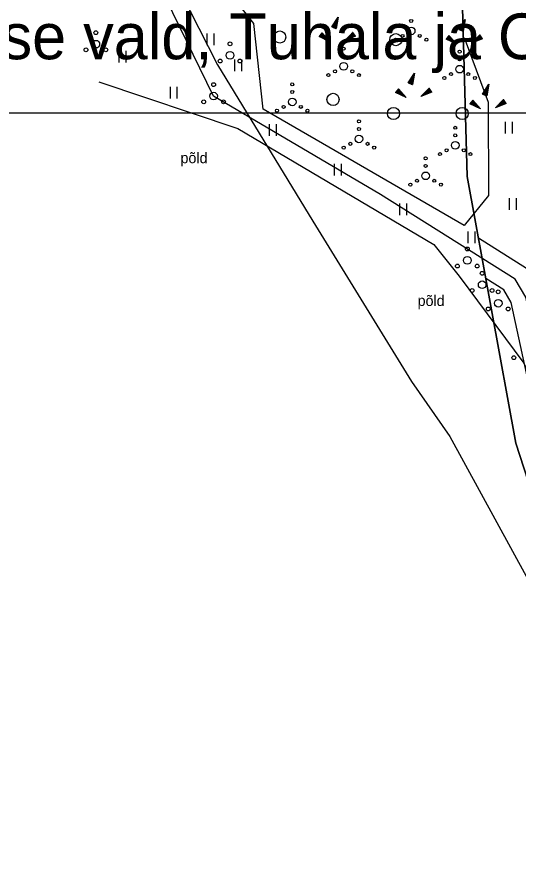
# Model space of a CAD drawing. Extents: x 554947 to 555436, y 6564938 to 6565792.
# Drawn here: x 555027.7 to 555060.6, y 6565555.5 to 6565611.2 of the extents above; entities that cross this region are included whole.
import ezdxf

# ---------------------------------------------------------------- set-up
doc = ezdxf.new("R2010")
doc.units = 0
for name, color, linetype in [('HALJASTUS', 7, 'Continuous'), ('KASUTUSALA', 7, 'Continuous'), ('KPKAABEL', 7, 'Continuous'), ('PIIR', 7, 'Continuous'), ('PR_SIDE', 7, 'Continuous'), ('PUU', 7, 'Continuous'), ('RELJEEF', 7, 'Continuous'), ('VORMISTUS_2', 7, 'Continuous')]:
    doc.layers.add(name, color=color, linetype=linetype)

msp = doc.modelspace()

# ---------------------------------------------------------------- linework, layer by layer
at = {"layer": 'HALJASTUS'}
for p, q in [((555040.145, 6565610.116), (555040.145, 6565609.355)), ((555040.6, 6565610.116), (555040.6, 6565609.355)), ((555034.383, 6565608.969), (555034.383, 6565608.208)), ((555034.838, 6565608.969), (555034.838, 6565608.208)), ((555041.957, 6565608.406), (555041.957, 6565607.645)), ((555042.412, 6565608.406), (555042.412, 6565607.645)), ((555037.737, 6565606.607), (555037.737, 6565605.846)), ((555038.192, 6565606.607), (555038.192, 6565605.846)), ((555044.239, 6565604.173), (555044.239, 6565603.412)), ((555044.694, 6565604.173), (555044.694, 6565603.412)), ((555059.719, 6565604.314), (555059.719, 6565603.553)), ((555060.174, 6565604.314), (555060.174, 6565603.553)), ((555048.509, 6565601.572), (555048.509, 6565600.811)), ((555048.964, 6565601.572), (555048.964, 6565600.811)), ((555059.968, 6565599.32), (555059.968, 6565598.559)), ((555060.423, 6565599.32), (555060.423, 6565598.559)), ((555052.779, 6565598.971), (555052.779, 6565598.209)), ((555053.234, 6565598.971), (555053.234, 6565598.209)), ((555057.264, 6565597.135), (555057.264, 6565596.374)), ((555057.719, 6565597.135), (555057.719, 6565596.374))]:
    msp.add_line(p, q, dxfattribs=at)
for points in [[(555057.023, 6565609.855), (555058.586, 6565605.616), (555058.613, 6565599.497), (555057.015, 6565597.532), (555043.839, 6565605.146), (555043.23, 6565610.761), (555037.198, 6565618.427), (555042.201, 6565623.493), (555040.415, 6565628.763), (555044.392, 6565634.613), (555048.032, 6565636.033)], [(555033.078, 6565606.955), (555042.182, 6565603.884), (555055.024, 6565596.272), (555056.694, 6565594.201), (555060.942, 6565588.507), (555062.867, 6565584.513)]]:
    msp.add_lwpolyline(points, dxfattribs=at)
for centre, radius in [((555053.549, 6565610.933), 0.1), ((555044.928, 6565609.882), 0.4), ((555053.549, 6565610.283), 0.25), ((555052.549, 6565609.708), 0.4), ((555052.549, 6565609.708), 0.1), ((555052.984, 6565609.958), 0.1), ((555054.114, 6565609.958), 0.1), ((555054.549, 6565609.708), 0.1), ((555049.12, 6565609.112), 0.1), ((555049.12, 6565608.612), 0.1), ((555056.725, 6565608.924), 0.1), ((555049.12, 6565607.962), 0.25), ((555056.725, 6565607.774), 0.25), ((555056.725, 6565608.424), 0.1), ((555048.12, 6565607.387), 0.1), ((555048.555, 6565607.637), 0.1), ((555049.685, 6565607.637), 0.1), ((555050.12, 6565607.387), 0.1), ((555056.16, 6565607.449), 0.1), ((555057.29, 6565607.449), 0.1), ((555055.725, 6565607.199), 0.1), ((555057.725, 6565607.199), 0.1), ((555045.748, 6565606.779), 0.1), ((555045.748, 6565606.279), 0.1), ((555045.748, 6565605.629), 0.25), ((555048.425, 6565605.793), 0.4), ((555045.183, 6565605.304), 0.1), ((555046.313, 6565605.304), 0.1), ((555052.386, 6565604.865), 0.4), ((555056.894, 6565604.865), 0.4), ((555044.748, 6565605.054), 0.1), ((555046.748, 6565605.054), 0.1), ((555050.122, 6565604.356), 0.1), ((555050.122, 6565603.856), 0.1), ((555056.435, 6565603.933), 0.1), ((555050.122, 6565603.206), 0.25), ((555056.435, 6565602.783), 0.25), ((555056.435, 6565603.433), 0.1), ((555049.122, 6565602.631), 0.1), ((555049.557, 6565602.881), 0.1), ((555050.687, 6565602.881), 0.1), ((555051.122, 6565602.631), 0.1), ((555055.87, 6565602.458), 0.1), ((555057, 6565602.458), 0.1), ((555054.496, 6565601.934), 0.1), ((555055.435, 6565602.208), 0.1), ((555057.435, 6565602.208), 0.1), ((555054.496, 6565601.434), 0.1), ((555054.496, 6565600.784), 0.25), ((555053.496, 6565600.209), 0.1), ((555053.931, 6565600.459), 0.1), ((555055.061, 6565600.459), 0.1), ((555055.496, 6565600.209), 0.1)]:
    msp.add_circle(centre, radius, dxfattribs=at)
at = {"layer": 'KASUTUSALA'}
msp.add_lwpolyline([(555076.534, 6565548.031), (555070.062, 6565562.678), (555061.905, 6565584.227), (555060.115, 6565592.474), (555059.634, 6565593.305), (555058.443, 6565594.054), (555057.954, 6565596.723), (555061.117, 6565594.735), (555062.003, 6565593.204), (555063.828, 6565584.797), (555071.913, 6565563.437), (555078.324, 6565548.927)], dxfattribs=at)
at = {"layer": 'KPKAABEL'}
msp.add_lwpolyline([(555022.085, 6565654.913), (555021.622, 6565652.627), (555021.526, 6565649.765), (555022.786, 6565647.231), (555026.485, 6565641.465), (555030.606, 6565629.728), (555035.378, 6565618.813), (555040.844, 6565608.057), (555047.089, 6565597.805), (555053.567, 6565587.292), (555056.073, 6565583.696), (555062.108, 6565572.667), (555068.248, 6565560.982), (555073.771, 6565549.852), (555080.106, 6565537.978), (555085.958, 6565527.605), (555092.403, 6565515.607), (555098.402, 6565504.536), (555104.641, 6565492.438), (555110.839, 6565480.82), (555116.697, 6565469.072), (555121.821, 6565458.116), (555126.894, 6565446.731), (555132.737, 6565435.388)], dxfattribs=at)
at = {"layer": 'PIIR'}
for points in [[(555016.055, 6565654.913), (555030.24, 6565648.23), (555043.11, 6565640.11), (555053.62, 6565632.14), (555056.61, 6565622.91), (555057.22, 6565600.73), (555060.42, 6565583.26), (555065.78, 6565566.7), (555076.76, 6565542.38), (555113.82, 6565475.68), (554946.63, 6565420.78), (554981.01, 6565316.76), (555160.07, 6565375.54), (555166.64, 6565360.5), (555167.67, 6565357.913)], [(555144.16, 6565410.6), (555124.27, 6565454.45), (555113.82, 6565475.68), (555076.76, 6565542.38), (555065.78, 6565566.7), (555060.42, 6565583.26), (555057.22, 6565600.73), (555056.61, 6565622.91), (555063.43, 6565647.29), (555114.24, 6565634), (555129.77, 6565611.2), (555130.73, 6565621.32), (555138.66, 6565615.26), (555160.12, 6565598.86), (555193.24, 6565604.68), (555193.7, 6565602.7), (555225.47, 6565605.89), (555234.35, 6565605.6), (555251.24, 6565598.48), (555330.71, 6565538.85), (555343.81, 6565536.56), (555350.68, 6565540.44), (555361.56, 6565549.57), (555393.069, 6565582.099)]]:
    msp.add_lwpolyline(points, dxfattribs=at)
at = {"layer": 'PR_SIDE'}
msp.add_lwpolyline([(555136.7, 6565433.435), (555128.282, 6565452.724), (555120.742, 6565469.061), (555112.406, 6565484.723), (555103.739, 6565501.239), (555091.881, 6565522.261), (555081.894, 6565540.539), (555077.43, 6565548.48), (555070.988, 6565563.058), (555062.867, 6565584.513), (555061.059, 6565592.839), (555060.376, 6565594.02), (555051.547, 6565599.57), (555040.593, 6565606.013), (555035.25, 6565616.948), (555028.135, 6565630.971), (555028.178, 6565632.46), (555043.563, 6565658.774)], dxfattribs=at)
at = {"layer": 'PUU'}
for centre, radius in [((555032.872, 6565610.163), 0.125), ((555032.222, 6565609.038), 0.125), ((555032.872, 6565609.413), 0.25), ((555033.522, 6565609.038), 0.125), ((555041.669, 6565609.433), 0.125), ((555041.669, 6565608.683), 0.25), ((555041.019, 6565608.308), 0.125), ((555042.319, 6565608.308), 0.125), ((555040.593, 6565606.763), 0.125), ((555040.593, 6565606.013), 0.25), ((555039.943, 6565605.638), 0.125), ((555041.243, 6565605.638), 0.125), ((555057.23, 6565595.993), 0.125), ((555057.23, 6565595.243), 0.25), ((555056.579, 6565594.868), 0.125), ((555057.88, 6565594.868), 0.125), ((555058.203, 6565594.394), 0.125), ((555058.203, 6565593.644), 0.25), ((555057.552, 6565593.269), 0.125), ((555058.853, 6565593.269), 0.125), ((555059.256, 6565593.182), 0.125), ((555059.256, 6565592.432), 0.25), ((555058.606, 6565592.057), 0.125), ((555059.906, 6565592.057), 0.125), ((555060.284, 6565588.861), 0.125)]:
    msp.add_circle(centre, radius, dxfattribs=at)
at = {"layer": 'RELJEEF'}
for p, q in [((555048.34, 6565610.548), (555048.76, 6565611.188)), ((555048.44, 6565610.698), (555048.69, 6565610.803)), ((555048.49, 6565610.773), (555048.615, 6565610.828)), ((555048.54, 6565610.848), (555048.71, 6565610.923)), ((555048.59, 6565610.923), (555048.72, 6565610.983)), ((555048.615, 6565610.828), (555048.7, 6565610.863)), ((555048.76, 6565611.188), (555048.62, 6565610.433)), ((555048.635, 6565610.998), (555048.735, 6565611.038)), ((555048.685, 6565611.073), (555048.745, 6565611.098)), ((555048.735, 6565611.148), (555048.755, 6565611.158)), ((555056.668, 6565610.381), (555057.088, 6565611.021)), ((555056.918, 6565610.756), (555057.048, 6565610.816)), ((555057.088, 6565611.021), (555056.948, 6565610.266)), ((555056.963, 6565610.831), (555057.063, 6565610.871)), ((555057.013, 6565610.906), (555057.073, 6565610.931)), ((555057.063, 6565610.981), (555057.083, 6565610.991)), ((555048.34, 6565610.548), (555048.665, 6565610.688)), ((555048.34, 6565610.548), (555048.62, 6565610.433)), ((555048.34, 6565610.548), (555048.34, 6565610.548)), ((555048.39, 6565610.623), (555048.675, 6565610.743)), ((555048.405, 6565610.523), (555048.655, 6565610.628)), ((555048.47, 6565610.493), (555048.645, 6565610.568)), ((555048.54, 6565610.468), (555048.635, 6565610.508)), ((555048.605, 6565610.443), (555048.62, 6565610.448)), ((555056.668, 6565610.381), (555056.993, 6565610.521)), ((555056.668, 6565610.381), (555056.948, 6565610.266)), ((555056.668, 6565610.381), (555056.668, 6565610.381)), ((555056.718, 6565610.456), (555057.003, 6565610.576)), ((555056.733, 6565610.356), (555056.983, 6565610.461)), ((555056.768, 6565610.531), (555057.018, 6565610.636)), ((555056.798, 6565610.326), (555056.973, 6565610.401)), ((555056.818, 6565610.606), (555056.943, 6565610.661)), ((555056.868, 6565610.681), (555057.038, 6565610.756)), ((555056.868, 6565610.301), (555056.963, 6565610.341)), ((555056.933, 6565610.276), (555056.948, 6565610.281)), ((555056.943, 6565610.661), (555057.028, 6565610.696)), ((555047.698, 6565610.147), (555047.513, 6565609.907)), ((555048.203, 6565609.577), (555047.513, 6565609.907)), ((555047.523, 6565609.922), (555047.528, 6565609.902)), ((555047.568, 6565609.977), (555047.583, 6565609.877)), ((555047.613, 6565610.037), (555047.638, 6565609.852)), ((555047.653, 6565610.092), (555047.688, 6565609.822)), ((555047.698, 6565610.147), (555048.203, 6565609.577)), ((555047.698, 6565610.147), (555047.743, 6565609.797)), ((555047.698, 6565610.147), (555047.698, 6565610.147)), ((555047.758, 6565610.082), (555047.798, 6565609.772)), ((555047.818, 6565610.012), (555047.853, 6565609.747)), ((555047.878, 6565609.947), (555047.893, 6565609.807)), ((555047.893, 6565609.807), (555047.908, 6565609.717)), ((555047.933, 6565609.877), (555047.963, 6565609.692)), ((555047.993, 6565609.812), (555048.013, 6565609.667)), ((555048.053, 6565609.742), (555048.068, 6565609.642)), ((555048.113, 6565609.677), (555048.123, 6565609.612)), ((555049.177, 6565609.642), (555049.717, 6565610.187)), ((555049.887, 6565609.937), (555049.177, 6565609.642)), ((555049.302, 6565609.692), (555049.242, 6565609.707)), ((555049.387, 6565609.727), (555049.282, 6565609.747)), ((555049.467, 6565609.762), (555049.327, 6565609.792)), ((555049.552, 6565609.797), (555049.367, 6565609.832)), ((555049.502, 6565609.857), (555049.412, 6565609.877)), ((555049.717, 6565609.867), (555049.452, 6565609.917)), ((555049.802, 6565609.902), (555049.497, 6565609.962)), ((555049.637, 6565609.832), (555049.502, 6565609.857)), ((555049.887, 6565609.937), (555049.537, 6565610.002)), ((555049.847, 6565609.992), (555049.582, 6565610.047)), ((555049.807, 6565610.052), (555049.622, 6565610.087)), ((555049.767, 6565610.112), (555049.667, 6565610.132)), ((555049.727, 6565610.172), (555049.707, 6565610.172)), ((555049.887, 6565609.937), (555049.717, 6565610.187)), ((555049.887, 6565609.937), (555049.887, 6565609.937)), ((555056.027, 6565609.98), (555055.842, 6565609.74)), ((555056.532, 6565609.41), (555055.842, 6565609.74)), ((555055.852, 6565609.755), (555055.857, 6565609.735)), ((555055.897, 6565609.81), (555055.912, 6565609.71)), ((555055.942, 6565609.87), (555055.967, 6565609.685)), ((555055.982, 6565609.925), (555056.017, 6565609.655)), ((555056.027, 6565609.98), (555056.532, 6565609.41)), ((555056.027, 6565609.98), (555056.072, 6565609.63)), ((555056.027, 6565609.98), (555056.027, 6565609.98)), ((555056.087, 6565609.915), (555056.127, 6565609.605)), ((555056.147, 6565609.845), (555056.182, 6565609.58)), ((555056.207, 6565609.78), (555056.222, 6565609.64)), ((555056.262, 6565609.71), (555056.292, 6565609.525)), ((555057.506, 6565609.475), (555058.046, 6565610.02)), ((555058.216, 6565609.77), (555057.506, 6565609.475)), ((555057.831, 6565609.69), (555057.741, 6565609.71)), ((555058.046, 6565609.7), (555057.781, 6565609.75)), ((555058.131, 6565609.735), (555057.826, 6565609.795)), ((555057.966, 6565609.665), (555057.831, 6565609.69)), ((555058.216, 6565609.77), (555057.866, 6565609.835)), ((555058.176, 6565609.825), (555057.911, 6565609.88)), ((555058.136, 6565609.885), (555057.951, 6565609.92)), ((555058.096, 6565609.945), (555057.996, 6565609.965)), ((555058.056, 6565610.005), (555058.036, 6565610.005)), ((555058.216, 6565609.77), (555058.046, 6565610.02)), ((555058.216, 6565609.77), (555058.216, 6565609.77)), ((555048.173, 6565609.607), (555048.178, 6565609.587)), ((555049.217, 6565609.657), (555049.202, 6565609.662)), ((555056.222, 6565609.64), (555056.237, 6565609.55)), ((555056.322, 6565609.645), (555056.342, 6565609.5)), ((555056.382, 6565609.575), (555056.397, 6565609.475)), ((555056.442, 6565609.51), (555056.452, 6565609.445)), ((555056.502, 6565609.44), (555056.507, 6565609.42)), ((555057.546, 6565609.49), (555057.531, 6565609.495)), ((555057.631, 6565609.525), (555057.571, 6565609.54)), ((555057.716, 6565609.56), (555057.611, 6565609.58)), ((555057.796, 6565609.595), (555057.656, 6565609.625)), ((555057.881, 6565609.63), (555057.696, 6565609.665)), ((555053.353, 6565606.88), (555053.773, 6565607.52)), ((555053.773, 6565607.52), (555053.633, 6565606.765)), ((555053.748, 6565607.48), (555053.768, 6565607.49)), ((555053.353, 6565606.88), (555053.678, 6565607.02)), ((555053.403, 6565606.955), (555053.688, 6565607.075)), ((555053.418, 6565606.855), (555053.668, 6565606.96)), ((555053.453, 6565607.03), (555053.703, 6565607.135)), ((555053.483, 6565606.825), (555053.658, 6565606.9)), ((555053.503, 6565607.105), (555053.628, 6565607.16)), ((555053.553, 6565607.18), (555053.723, 6565607.255)), ((555053.603, 6565607.255), (555053.733, 6565607.315)), ((555053.628, 6565607.16), (555053.713, 6565607.195)), ((555053.648, 6565607.33), (555053.748, 6565607.37)), ((555053.698, 6565607.405), (555053.758, 6565607.43)), ((555052.712, 6565606.48), (555052.527, 6565606.24)), ((555052.627, 6565606.37), (555052.652, 6565606.185)), ((555052.667, 6565606.425), (555052.702, 6565606.155)), ((555052.712, 6565606.48), (555053.217, 6565605.91)), ((555052.712, 6565606.48), (555052.757, 6565606.13)), ((555052.712, 6565606.48), (555052.712, 6565606.48)), ((555052.772, 6565606.415), (555052.812, 6565606.105)), ((555052.832, 6565606.345), (555052.867, 6565606.08)), ((555053.353, 6565606.88), (555053.633, 6565606.765)), ((555053.353, 6565606.88), (555053.353, 6565606.88)), ((555053.553, 6565606.8), (555053.648, 6565606.84)), ((555053.618, 6565606.775), (555053.633, 6565606.78)), ((555054.191, 6565605.975), (555054.731, 6565606.52)), ((555054.901, 6565606.27), (555054.551, 6565606.335)), ((555054.861, 6565606.325), (555054.596, 6565606.38)), ((555054.821, 6565606.385), (555054.636, 6565606.42)), ((555054.781, 6565606.445), (555054.681, 6565606.465)), ((555054.741, 6565606.505), (555054.721, 6565606.505)), ((555054.901, 6565606.27), (555054.731, 6565606.52)), ((555058.231, 6565606.142), (555058.651, 6565606.782)), ((555058.281, 6565606.217), (555058.566, 6565606.337)), ((555058.331, 6565606.292), (555058.581, 6565606.397)), ((555058.381, 6565606.367), (555058.506, 6565606.422)), ((555058.431, 6565606.442), (555058.601, 6565606.517)), ((555058.481, 6565606.517), (555058.611, 6565606.577)), ((555058.506, 6565606.422), (555058.591, 6565606.457)), ((555058.651, 6565606.782), (555058.511, 6565606.027)), ((555058.526, 6565606.592), (555058.626, 6565606.632)), ((555058.576, 6565606.667), (555058.636, 6565606.692)), ((555058.626, 6565606.742), (555058.646, 6565606.752)), ((555053.217, 6565605.91), (555052.527, 6565606.24)), ((555052.537, 6565606.255), (555052.542, 6565606.235)), ((555052.582, 6565606.31), (555052.597, 6565606.21)), ((555052.892, 6565606.28), (555052.907, 6565606.14)), ((555052.907, 6565606.14), (555052.922, 6565606.05)), ((555052.947, 6565606.21), (555052.977, 6565606.025)), ((555053.007, 6565606.145), (555053.027, 6565606)), ((555053.067, 6565606.075), (555053.082, 6565605.975)), ((555053.127, 6565606.01), (555053.137, 6565605.945)), ((555053.187, 6565605.94), (555053.192, 6565605.92)), ((555054.901, 6565606.27), (555054.191, 6565605.975)), ((555054.231, 6565605.99), (555054.216, 6565605.995)), ((555054.316, 6565606.025), (555054.256, 6565606.04)), ((555054.401, 6565606.06), (555054.296, 6565606.08)), ((555054.481, 6565606.095), (555054.341, 6565606.125)), ((555054.566, 6565606.13), (555054.381, 6565606.165)), ((555054.516, 6565606.19), (555054.426, 6565606.21)), ((555054.731, 6565606.2), (555054.466, 6565606.25)), ((555054.816, 6565606.235), (555054.511, 6565606.295)), ((555054.651, 6565606.165), (555054.516, 6565606.19)), ((555054.901, 6565606.27), (555054.901, 6565606.27)), ((555058.231, 6565606.142), (555058.556, 6565606.282)), ((555058.231, 6565606.142), (555058.511, 6565606.027)), ((555058.231, 6565606.142), (555058.231, 6565606.142)), ((555058.296, 6565606.117), (555058.546, 6565606.222)), ((555058.361, 6565606.087), (555058.536, 6565606.162)), ((555058.431, 6565606.062), (555058.526, 6565606.102)), ((555058.496, 6565606.037), (555058.511, 6565606.042)), ((555059.069, 6565605.236), (555059.609, 6565605.781)), ((555059.779, 6565605.531), (555059.609, 6565605.781)), ((555057.59, 6565605.741), (555057.405, 6565605.501)), ((555058.095, 6565605.171), (555057.405, 6565605.501)), ((555057.415, 6565605.516), (555057.42, 6565605.496)), ((555057.46, 6565605.571), (555057.475, 6565605.471)), ((555057.505, 6565605.631), (555057.53, 6565605.446)), ((555057.545, 6565605.686), (555057.58, 6565605.416)), ((555057.59, 6565605.741), (555058.095, 6565605.171)), ((555057.59, 6565605.741), (555057.635, 6565605.391)), ((555057.59, 6565605.741), (555057.59, 6565605.741)), ((555057.65, 6565605.676), (555057.69, 6565605.366)), ((555057.71, 6565605.606), (555057.745, 6565605.341)), ((555057.77, 6565605.541), (555057.785, 6565605.401)), ((555057.785, 6565605.401), (555057.8, 6565605.311)), ((555057.825, 6565605.471), (555057.855, 6565605.286)), ((555057.885, 6565605.406), (555057.905, 6565605.261)), ((555057.945, 6565605.336), (555057.96, 6565605.236)), ((555058.005, 6565605.271), (555058.015, 6565605.206)), ((555059.779, 6565605.531), (555059.069, 6565605.236)), ((555059.109, 6565605.251), (555059.094, 6565605.256)), ((555059.194, 6565605.286), (555059.134, 6565605.301)), ((555059.279, 6565605.321), (555059.174, 6565605.341)), ((555059.359, 6565605.356), (555059.219, 6565605.386)), ((555059.444, 6565605.391), (555059.259, 6565605.426)), ((555059.394, 6565605.451), (555059.304, 6565605.471)), ((555059.609, 6565605.461), (555059.344, 6565605.511)), ((555059.694, 6565605.496), (555059.389, 6565605.556)), ((555059.529, 6565605.426), (555059.394, 6565605.451)), ((555059.779, 6565605.531), (555059.429, 6565605.596)), ((555059.739, 6565605.586), (555059.474, 6565605.641)), ((555059.699, 6565605.646), (555059.514, 6565605.681)), ((555059.659, 6565605.706), (555059.559, 6565605.726)), ((555059.619, 6565605.766), (555059.599, 6565605.766)), ((555059.779, 6565605.531), (555059.779, 6565605.531)), ((555058.065, 6565605.201), (555058.07, 6565605.181))]:
    msp.add_line(p, q, dxfattribs=at)
at = {"layer": 'VORMISTUS_2'}
msp.add_lwpolyline([(555186.863, 6565394.913), (555021.863, 6565394.913), (555021.863, 6565604.913), (555186.863, 6565604.913)], close=True, dxfattribs=at)

# ---------------------------------------------------------------- texts
at = {"layer": 'HALJASTUS'}
for p in [(555038.423, 6565601.611), (555053.97, 6565592.252)]:
    msp.add_text('põld', height=0.7, rotation=359.9544, dxfattribs=at).set_placement(p)
at = {"layer": 'VORMISTUS_2'}
msp.add_text('Kose vald, Tuhala ja Otiveski elurajooni sideühendus', height=3, rotation=360, dxfattribs=at).set_placement((555021.782, 6565608.425))

doc.saveas('drawing.dxf')
